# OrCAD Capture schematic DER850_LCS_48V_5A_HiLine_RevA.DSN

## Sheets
1 PAGE2: size B
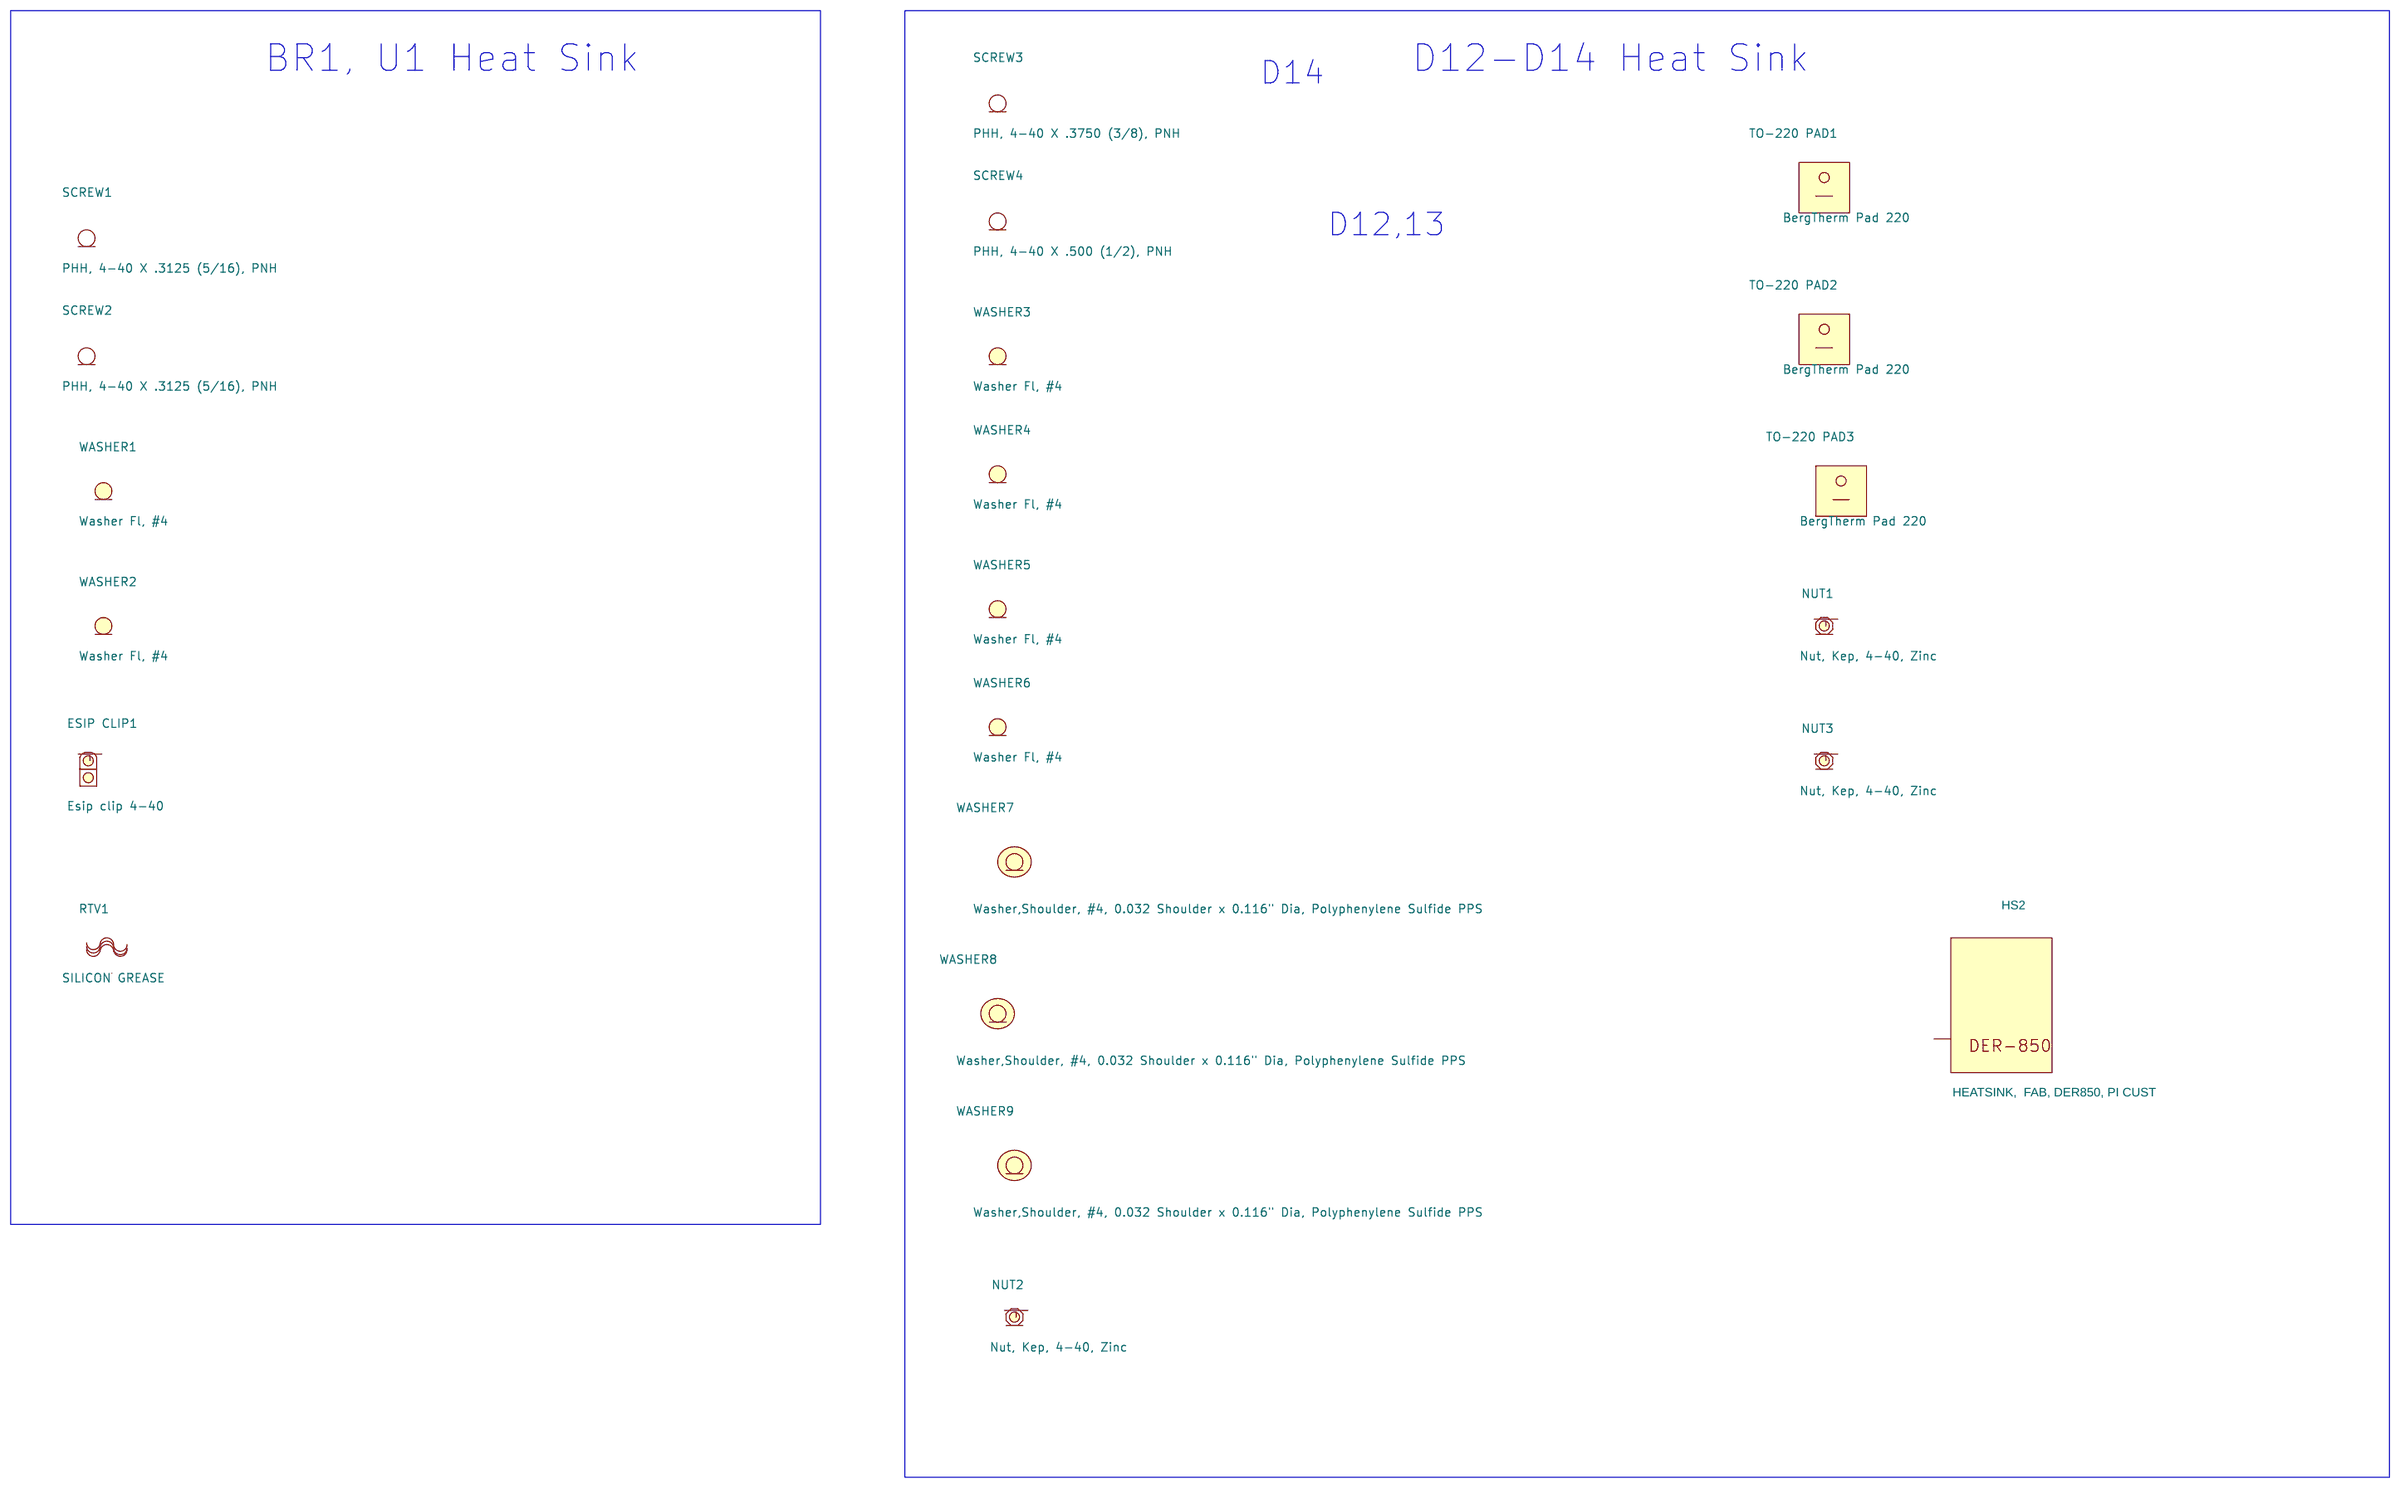
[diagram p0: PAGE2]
2 PAGE1: size C; title: DER-447; rev: D
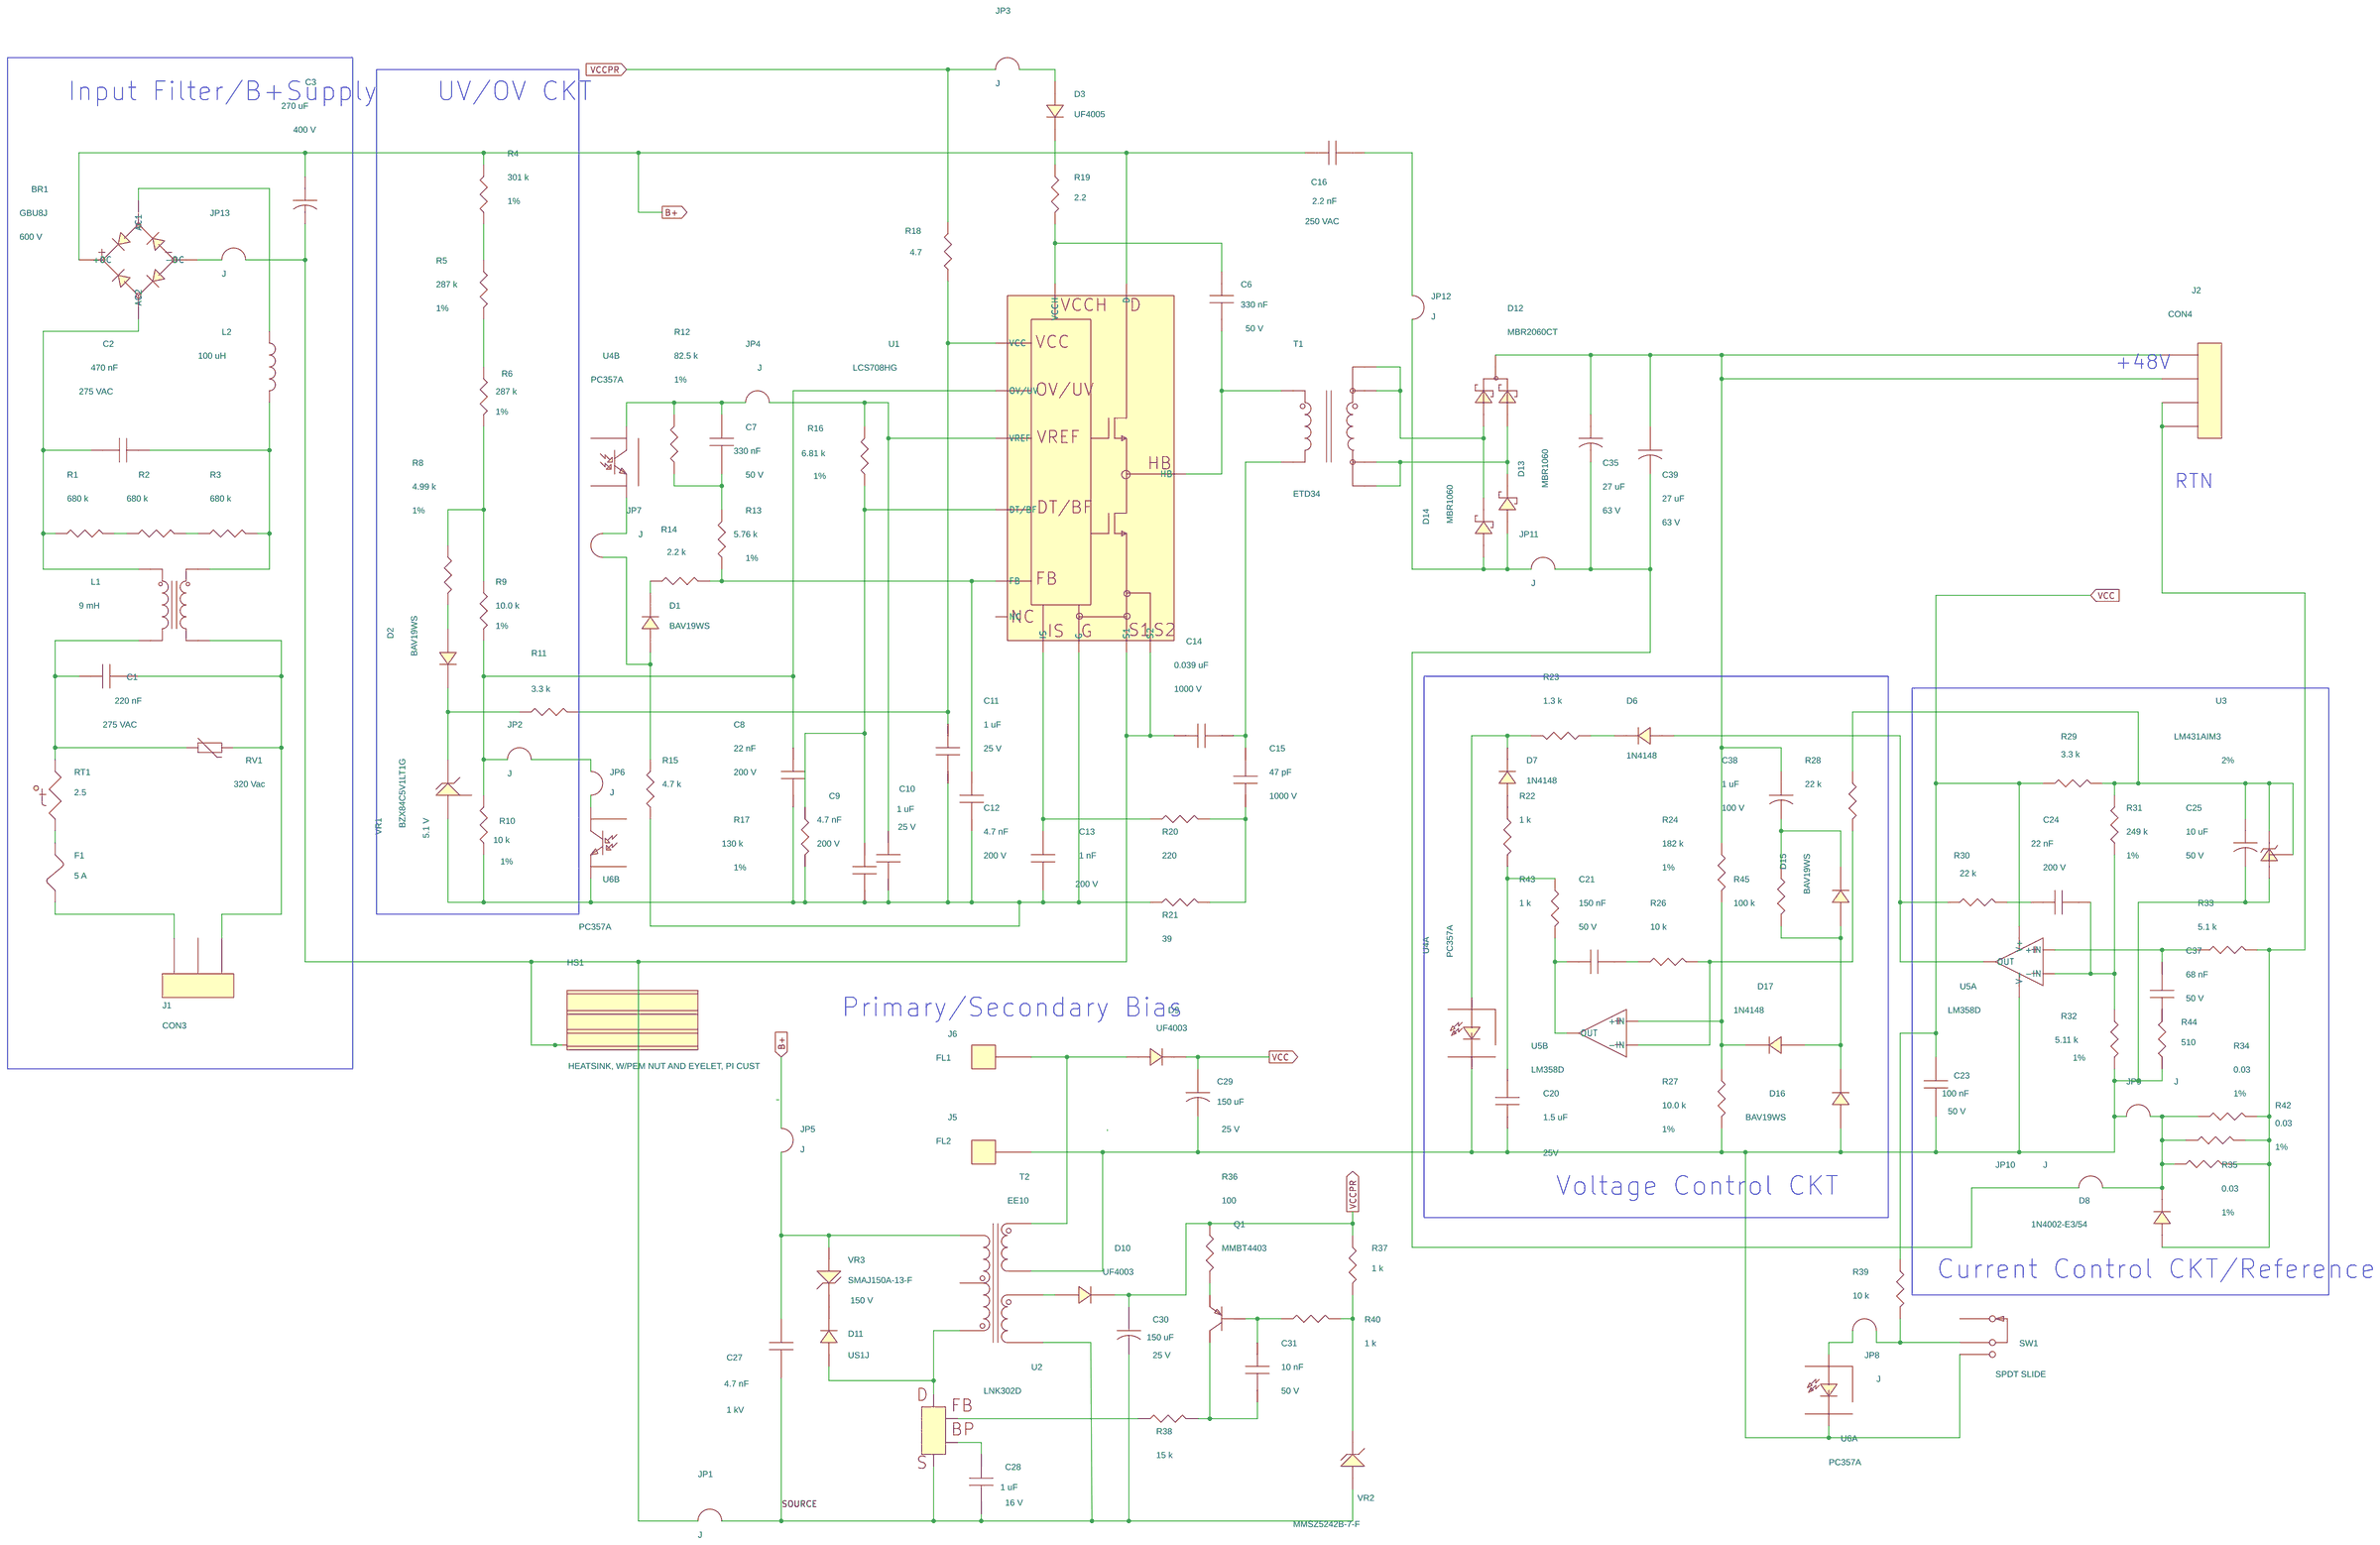
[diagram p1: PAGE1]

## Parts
sheet PAGE1
BR1  GBU8J  [pidaxbridgegbu8]
C1  220 nF  [pinpxcaprad720x340590040]
C2  470 nF  [pinpcaprad760x380590050]
C3  270 uF  [pipolcapclyd948ls394080]
C6  330 nF  [pinpcaprad200x100200030]
C7  330 nF  [pismc0805]
C8  22 nF  [pismc0805]
C9  4.7 nF  [pismc0805]
C10  1 uF  [pismc1206]
C11  1 uF  [pismc1206]
C12  4.7 nF  [pismc0805]
C13  1 nF  [pismc0805]
C14  0.039 uF  [pinpcap23x8x20mmLSd040]
C15  47 pF  [pinpcaprad370x156250040]
C16  2.2 nF  [pinpycaprad540x290ls400040]
C20  1.5 uF  [pismc1206]
C21  150 nF  [pismc0805]
C23  100 nF  [pismc0805]
C24  22 nF  [pismc0805]
C25  10 uF  [pipolcapclyd200ls80030]
C27  4.7 nF  [pinpcaprad370x156250040]
C28  1 uF  [pismc0603]
C29  150 uF  [pipolcapcyld250ls100030]
C30  150 uF  [pipolcapcyld250ls100030]
C31  10 nF  [pismc0805]
C35  27 uF  [pipolcapclyd320ls140030]
C37  68 nF  [pismc0805]
C38  1 uF  [pipolcapclyd200ls80030]
C39  27 uF  [pipolcapclyd320ls140030]
D1  BAV19WS  [pismsod323]
D2  BAV19WS  [pismsod323]
D3  UF4005  [pidax475x125040do41]
D6  1N4148  [pidax375x070030do35]
D7  1N4148  [pidax375x070030do35]
D8  1N4002-E3/54  [pidv200x110x040do41]
D9  UF4003  [pidv200x110x040do41]
D10  UF4003  [pidv200x110x040do41]
D11  US1J  [pismdsma]
D12  MBR2060CT  [pidvto2203vf1]
D13  MBR1060  [pidvt0220acreva]
D14  MBR1060  [pidvt0220acreva]
D15  BAV19WS  [pismsod323]
D16  BAV19WS  [pismsod323]
D17  1N4148  [pidax375x070030do35]
F1  5 A  [pi_tr5_submin_fuse]
HS1  HEATSINK, W/PEM NUT AND EYELET, PI CUST  [pi_hs_der447_bridge_eSIP]
J1  CON3  [pi_hdr_3pin_156_lock]
J2  CON4  [PI_HDR_4PIN]
J5  FL2  [pi_hole_30awg]
J6  FL1  [pi_hole_30awg]
JP1  J  [pi_jumper700]
JP2  J  [pi_jumper400]
JP3  J  [pi_jumper900]
JP4  J  [pi_jumper300]
JP5  J  [pi_jumper1800]
JP6  J  [pi_jumper200]
JP7  J  [pi_jumper200]
JP8  J  [pi_jumper900]
JP9  J  [pi_jumper300]
JP10  J  [pi_jumper600-18awg-sld]
JP11  J  [pi_jumper300-18awg-sld]
JP12  J  [pi_jumper800]
JP13  J  [pi_jumper900-18awg-sld]
L1  9 mH  [pi_ind_4p_500x1050ls450d46]
L2  100 uH  [pi2p455x1062ls315d60]
Q1  MMBT4403  [pismsot23132]
R1  680 k  [pismr1206]
R2  680 k  [pismr1206]
R3  680 k  [pismr1206]
R4  301 k  [pi14wresd100ls400d030]
R5  287 k  [pismr1206]
R6  287 k  [pismr1206]
R8  4.99 k  [pismr0805]
R9  10.0 k  [pismr1206]
R10  10 k  [pismr0805]
R11  3.3 k  [pismr0805]
R12  82.5 k  [pismr0805]
R13  5.76 k  [pismr0805]
R14  2.2 k  [pismr1206]
R15  4.7 k  [pismr0805]
R16  6.81 k  [pi14wresd100ls400d030]
R17  130 k  [pismr0805]
R18  4.7  [pismr1206]
R19  2.2  [pi14wresd100ls400d030]
R20  220  [pismr0603]
R21  39  [pismr0805]
R22  1 k  [pismr0805]
R23  1.3 k  [pi14wresd100ls400d030]
R24  182 k  [pi14wresd100ls500d030]
R26  10 k  [pismr0805]
R27  10.0 k  [pi14wresd100ls400d030]
R28  22 k  [pi14wresd100ls500d030]
R29  3.3 k  [pi14wvresd100ls100d030]
R30  22 k  [pismr0805]
R31  249 k  [pismr0805]
R32  5.11 k  [pismr0805]
R33  5.1 k  [pi14wresd100ls400d030]
R34  0.03  [pismr1206]
R35  0.03  [pismr1206]
R36  100  [pismr0603]
R37  1 k  [pismr0603]
R38  15 k  [pismr0805]
R39  10 k  [pismr0805]
R40  1 k  [pismr0603]
R42  0.03  [pismr1206]
R43  1 k  [pismr0805]
R44  510  [pismr0603]
R45  100 k  [pismr0805]
RT1  2.5  [pi_rad180x395ls235d031]
RV1  320 Vac  [pidisc675x225ls335x140040]
SW1  SPDT SLIDE  [pi_switch_spdt_slide_pcbm_1]
T1  ETD34  [pi_xfrmr_DER850_LLC]
T2  EE10  [pi_xfrmr_DER850_Bias]
U1  LCS708HG  [pi_ic_esip16-13_oval_slot]
U2  LNK302D  [pismso8dnshort5678]
U3  LM431AIM3  [pismsot23123]
U4  PC357A  [pi_4_smd]  (sections A,B)
U5  LM358D  [pismso8]  (sections A,B)
U6  PC357A  [pi_4_smd]  (sections A,B)
VR1  BZX84C5V1LT1G  [pismsot23123]
VR2  MMSZ5242B-7-F  [pi_sm_sod-123_12]
VR3  SMAJ150A-13-F  [pismdo214ac12]
sheet PAGE2
ESIP CLIP1  Esip clip 4-40
HS2  HEATSINK,  FAB, DER850, PI CUST  [pi_hs_1p_der850]
NUT1  Nut, Kep, 4-40, Zinc
NUT2  Nut, Kep, 4-40, Zinc
NUT3  Nut, Kep, 4-40, Zinc
RTV1  SILICON GREASE
SCREW1  PHH, 4-40 X .3125 (5/16), PNH
SCREW2  PHH, 4-40 X .3125 (5/16), PNH
SCREW3  PHH, 4-40 X .3750 (3/8), PNH
SCREW4  PHH, 4-40 X .500 (1/2), PNH
TO-220 PAD1  BergTherm Pad 220
TO-220 PAD2  BergTherm Pad 220
TO-220 PAD3  BergTherm Pad 220
WASHER1  Washer Fl, #4
WASHER2  Washer Fl, #4
WASHER3  Washer Fl, #4
WASHER4  Washer Fl, #4
WASHER5  Washer Fl, #4
WASHER6  Washer Fl, #4
WASHER7  Washer,Shoulder, #4, 0.032 Shoulder x 0.116" Dia, Polyphenylene Sulfide PPS
WASHER8  Washer,Shoulder, #4, 0.032 Shoulder x 0.116" Dia, Polyphenylene Sulfide PPS
WASHER9  Washer,Shoulder, #4, 0.032 Shoulder x 0.116" Dia, Polyphenylene Sulfide PPS

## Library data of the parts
BR1 = DISCRETE_BRIDGE_+~~-: Disp_Voltage: 600 V; Part Number: 15-00720-00
C1 = CAP_NP: Disp_Voltage: 275 VAC; Part Number: 20-00386-00; Voltage: 275 VAC
C2 = CAP_NP: COMPGROUP: 1; Disp_Voltage: 275 VAC; PCB Editor PCBFP: pinpxcaprad720x340590040; Part Number: 20-00738-00; Tol: 20; Voltage: 275 VAC
C3 = CAP_POL: Disp_Voltage: 400 V; Part Number: 20-00783-00; Voltage: 400 V
C6 = CAP_NP: Disp_Voltage: 50 V; Part Number: 20-00935-00; Voltage: 50 V
C7 = CAP_NP: Disp_Voltage: 50 V; Part Number: 20-00895-00; Voltage: 50 V
C8 C24 = CAP_NP: Disp_Voltage: 200 V; Part Number: 20-00763-00; Voltage: 200 V
C9 = CAP_NP: COMPGROUP: 2; Disp_Voltage: 200 V; Layout PCB Footprint: PI_SM/C_0805; Part Number: 20-08570-00; Tol: 10; Voltage: 200 V
C10 C11 = CAP_NP: Disp_Voltage: 25 V; Part Number: 20-00897-00; Voltage: 25 V
C12 = CAP_NP: COMPGROUP: 2; Disp_Voltage: 200 V; Part Number: 20-08570-00; Tol: 10; Voltage: 200 V
C13 = CAP_NP: COMPGROUP: 2; Disp_Voltage: 200 V; Layout PCB Footprint: PI_SM/C_0805; Part Number: 20-00737-00; Tol: 10; Voltage: 200 V
C14 = CAP_NP: Disp_Voltage: 1000 V; Part Number: 20-01356-00; Voltage: 1000 V
C15 = CAP_NP: COMPGROUP: 2; Disp_Voltage: 1000 V; PCB Editor PCBFP: pinpcaprad180x160200030; Part Number: 20-08564-00; Tol: 5; Voltage: 1000 V
C16 = CAP_NP: ALT_SYMBOLS: pinpycaprad540x290ls400040h; Disp_Voltage: 250 VAC; FPLIST: pinpycaprad540x290ls400040,pinpycaprad540x290ls400040h; Part Number: 20-00376-00; Voltage: 250 VAC
C20 = CAP_NP: Disp_Voltage: 25V; Part Number: 20-01360-00; Voltage: 25 V
C21 = CAP_NP: Disp_Voltage: 50 V; Part Number: 20-01189-00; Voltage: 50 V
C23 = CAP_NP: Disp_Voltage: 50 V; Part Number: 20-00904-00; Voltage: 50 V
C25 = CAP_POL: ALT_SYMBOLS: pipolcapclyd200ls80030h; Disp_Voltage: 50 V; FPLIST: pipolcapclyd200ls80030,pipolcapclyd200ls80030h; Part Number: 20-00443-00; Voltage: 50 V
C27 = CAP_NP: COMPGROUP: 1; Disp_Voltage: 1 kV; Part Number: 20-00571-00; Voltage: 1 kV
C28 = CAP_NP: Disp_Voltage: 16 V; Part Number: 20-00540-00; Voltage: 16 V
C29 C30 = CAP_POL: COMPGROUP: 1; Disp_Voltage: 25 V; Part Number: 20-00096-00; Tol: 20; Voltage: 25 V
C31 = CAP_NP: COMPGROUP: 1; Disp_Voltage: 50 V; Part Number: 20-00965-00; Tol: 10; Voltage: 50 V
C35 C39 = CAP_POL: Disp_Voltage: 63 V; FPLIST: pipolcapclyd320ls140030,pipolcapclyd320ls140030430h; Part Number: 20-01354-00; Voltage: 63 V
C37 = CAP_NP: Disp_Voltage: 50 V; Part Number: 20-00231-00; Voltage: 50 V
C38 = CAP_POL: ALT_SYMBOLS: pipolcapclyd200ls80030h; Disp_Voltage: 100 V; FPLIST: pipolcapclyd200ls80030,pipolcapclyd200ls80030h; Part Number: 20-00448-00; Voltage: 100 V
D1 D2 D15 D16 = DIODE: Part Number: 15-00658-00
D3 = DIODE: ALT_SYMBOLS: pidax475x125040do41,pidax390x125040do41; FPLIST: pidv200x110x040do41,pidax475x125040do41,pidax390x125040do41; Part Number: 15-00109-00
D6 D7 D17 = DIODE: ALT_SYMBOLS: pidax375x070030do35,pidv100x080x030do35; FPLIST: pidv200x080x030do35,pidax375x070030do35,pidv100x080x030do35; Part Number: 15-00083-00
D8 = DIODE: ALT_SYMBOLS: pidax475x125040do41,pidv200x110x040do41wbead,pidax390x125040do41; FPLIST: pidv200x110x040do41,pidax475x125040do41,pidv200x110x040do41wbead,pidax390x125040do41; Part Number: 15-00792-00
D9 D10 = DIODE: ALT_SYMBOLS: pidax475x125040do41,pidv200x110x040do41wbead,pidax390x125040do41; COMPGROUP: 1; FPLIST: PI_DV/.200X.110X.040/DO_41,PI_DAX/.475X.125/.040/DO_41,PI_DV/.200X.110X.040/DO_41_WBEAD,PI_DAX/.390X.125/.040/DO_41; Part Number: 15-00107-00
D11 = DIODE: Part Number: 15-00494-00
D12 = DS_DUAL_CK_A_AC: ALT_SYMBOLS: pidvto2203; FPLIST: pidvto2203vf1,pidvto2203,pi_to220_mod_1; Part Number: 15-00346-00
D13 D14 = DIODE_SCHOTTKY: FPLIST: pidvt0220acreva,pi_to220aa_mod; Part Number: 15-00148-00
F1 = FUSE: COMPGROUP: 1; Part Number: 40-00005-00; Voltage: 250 V
HS1 = HS-PI_CUSTOM1: Part Number: 61-00182-01
J1 = CON3: COMPGROUP: 1; Part Number: 35-00110-00
J2 = CON4: COMPGROUP: 2; Part Number: 35-00003-00
J5 J6 = TERM_1Pin: Part Number: 35-00026-00
JP1 = JUMPER_1: Part Number: 65-00046-00
JP2 = JUMPER_1: Part Number: 65-00003-00
JP3 JP8 = JUMPER_1: Part Number: 65-00126-00
JP4 = JUMPER_1: Part Number: 65-00120-00
JP5 = JUMPER_1: Part Number: 65-00135-00
JP6 JP7 = JUMPER_1: Part Number: 65-00001-00
JP9 = JUMPER_1: Part Number: 65-00002-00
JP10 = JUMPER_1: Part Number: 65-00084-00
JP11 = JUMPER_1: Part Number: 65-00081-00
JP12 = JUMPER_1: Part Number: 65-00007-00
JP13 = JUMPER_1: Part Number: 65-00087-00
L1 = INDUCTOR_4P_REVB_0: Part Number: 30-00235-00
L2 = INDUCTOR: Part Number: 32-00210-00
Q1 = PNP_BEC: Part Number: 55-00060-00
R1-R3 = R: Part Number: 05-01420-00
R4 = R: ALT_SYMBOLS: pi14wvresd100ls125d030,pi14wvresd100ls150d030,pi14wvresd100ls200d030,pi14wvresd100ls300d030,pi14wresd100ls400d030,pi14wresd100ls500d030; Disp_Tol: 1%; FPLIST: pi14wvresd100ls100d030,pi14wvresd100ls125d030,pi14wvresd100ls150d030,pi14wvresd100ls200d030,pi14wvresd100ls300d030,pi14wresd100ls400d030,pi14wresd100ls500d030; Part Number: 05-02214-00
R5 R6 = R: COMPGROUP: 2; Disp_Tol: 1%; Part Number: 05-00429-00; Tol: 1%
R8 = R: COMPGROUP: 2; Disp_Tol: 1%; PCB Editor PCBFP: pismr1206; Part Number: 05-03373-00; Tol: 1%
R9 = R: COMPGROUP: 2; Disp_Tol: 1%; Part Number: 05-00289-00; Tol: 1%
R10 = R: Disp_Tol: 1%; Part Number: 05-00684-00
R11 = R: Part Number: 05-01531-00
R12 = R: Disp_Tol: 1%; Part Number: 05-00772-00
R13 = R: Disp_Tol: 1%; Part Number: 05-03379-00
R14 = R: Part Number: 05-01360-00
R15 = R: COMPGROUP: 2; Part Number: 05-01535-00; Tol: 5%
R16 = R: ALT_SYMBOLS: pi14wvresd100ls200d030,pi14wresd100ls400d030,pi14wresd100ls500d030; Disp_Tol: 1%; FPLIST: pi14wvresd100ls100d030,pi14wvresd100ls200d030,pi14wresd100ls400d030,pi14wresd100ls500d030; Part Number: 05-02056-00
R17 = R: Disp_Tol: 1%; Part Number: 05-00791-00
R18 = R: Part Number: 05-01296-00
R19 = R: ALT_SYMBOLS: pi14wvresd100ls125d030,pi14wvresd100ls150d030,pi14wvresd100ls200d030,pi14wvresd100ls300d030,pi14wresd100ls400d030,pi14wresd100ls500d030; FPLIST: pi14wvresd100ls100d030,pi14wvresd100ls125d030,pi14wvresd100ls150d030,pi14wvresd100ls200d030,pi14wvresd100ls300d030,pi14wresd100ls400d030,pi14wresd100ls500d030; Part Number: 05-02443-00
R20 = R: Part Number: 05-01672-00
R21 = R: Part Number: 05-01485-00
R22 R43 = R: Part Number: 05-01519-00
R23 = R: ALT_SYMBOLS: pi14wvresd100ls125d030,pi14wvresd100ls150d030,pi14wvresd100ls200d030,pi14wvresd100ls300d030,pi14wresd100ls400d030,pi14wresd100ls500d030; FPLIST: pi14wvresd100ls100d030,pi14wvresd100ls125d030,pi14wvresd100ls150d030,pi14wvresd100ls200d030,pi14wvresd100ls300d030,pi14wresd100ls400d030,pi14wresd100ls500d030; Part Number: 05-02510-00
R24 = R: ALT_SYMBOLS: pi14wvresd100ls200d030,pi14wresd100ls400d030,pi14wresd100ls500d030; Disp_Tol: 1%; FPLIST: pi14wvresd100ls100d030,pi14wvresd100ls200d030,pi14wresd100ls400d030,pi14wresd100ls500d030; Part Number: 05-02193-00
R26 R39 = R: Part Number: 05-01543-00
R27 = R: ALT_SYMBOLS: pi14wvresd100ls200d030,pi14wresd100ls400d030,pi14wresd100ls500d030; Disp_Tol: 1%; FPLIST: pi14wvresd100ls100d030,pi14wvresd100ls200d030,pi14wresd100ls400d030,pi14wresd100ls500d030; Part Number: 05-05421-00
R28 = R: ALT_SYMBOLS: pi14wvresd100ls125d030,pi14wvresd100ls150d030,pi14wvresd100ls200d030,pi14wvresd100ls300d030,pi14wresd100ls400d030,pi14wresd100ls500d030; FPLIST: pi14wvresd100ls100d030,pi14wvresd100ls125d030,pi14wvresd100ls150d030,pi14wvresd100ls200d030,pi14wvresd100ls300d030,pi14wresd100ls400d030,pi14wresd100ls500d030; Part Number: 05-02539-00
R29 = R: ALT_SYMBOLS: pi14wvresd100ls200d030,pi14wresd100ls400d030,pi14wresd100ls500d030; FPLIST: pi14wvresd100ls100d030,pi14wvresd100ls200d030,pi14wresd100ls400d030,pi14wresd100ls500d030; Part Number: 05-02519-00
R30 = R: Part Number: 05-01551-00
R31 = R: Disp_Tol: 1%; Part Number: 05-00818-00
R32 = R: Disp_Tol: 1%; Part Number: 05-03374-00
R33 = R: ALT_SYMBOLS: pi14wvresd100ls125d030,pi14wvresd100ls150d030,pi14wvresd100ls200d030,pi14wvresd100ls300d030,pi14wresd100ls400d030,pi14wresd100ls500d030; COMPGROUP: 5; FPLIST: pi14wvresd100ls100d030,pi14wvresd100ls125d030,pi14wvresd100ls150d030,pi14wvresd100ls200d030,pi14wvresd100ls300d030,pi14wresd100ls400d030,pi14wresd100ls500d030; PCB Editor PCBFP: pismr0805; Part Number: 05-02524-00; Tol: 1%
R34 R35 R42 = R: Disp_Tol: 1%; Part Number: 05-06436-00
R36 = R: Part Number: 05-01664-00
R37 R40 = R: Part Number: 05-01688-00
R38 = R: COMPGROUP: 1; Part Number: 05-01547-00
R44 = R: COMPGROUP: 5; PCB Editor PCBFP: pismr0805; Part Number: 05-01681-00; Tol: 1%
R45 = R: Part Number: 05-01567-00
RT1 = THERMISTOR: FPLIST: pi_rad180x395ls235d031,pirad550x410ls300040_h; Part Number: 90-00038-00
RV1 = VARISTOR: COMPGROUP: 1; Part Number: 85-00009-00
SW1 = SW_SLIDE-SPDT: Part Number: 66-00111-00
T1 = BETD_34_DER850_LLC: Part Number: 25-01172-00
T2 = BEE_10_DER850_Bias: Part Number: 25-01168-00
U1 = LC_SWITCH_Rev03: ALT_SYMBOLS: pi_ic_esip16-13_socket_sl0t,pi_ic_esip16-13_oval_slot; FPLIST: pi_ic_esip16-13_slot,pi_ic_esip16-13_socket_sl0t ,pi_ic_esip16-13_oval_slot; Part Number: 10-00515-00
U2 = LNK30X_SO8_DN: Part Number: 10-00232-00
U3 = TL431_SOT-23_CAR: Disp_Tol: 2%; Part Number: 45-00268-00; Tol: 2%
U4 U6 = OPTO_A_B: Part Number: 53-00033-00
U5 = LM358: Part Number: 45-00050-00
VR1 = DIODE_ZENERC2A1: Disp_Voltage: 5.1 V; Part Number: 15-000630-00
VR2 = DIODE_ZENER: COMPGROUP: 1; Part Number: 15-01090-00
VR3 = DIODE_ZENER: Disp_Voltage: 150 V; Part Number: 15-00428-00
ESIP CLIP1 = EsipClip_4-40: Part Number: 60-00037-00
HS2 = hs_1P_DER850: Part Number: 61-00271-01
NUT1-NUT3 = NUT_HEX_4-40: Part Number: 75-00068-00
RTV1 = RTV: Part Number: 66-00084-00
SCREW1 SCREW2 = SCR_4-40: Part Number: 75-00002-00
SCREW3 = SCR_4-40: Part Number: 75-00003-00
SCREW4 = SCR_4-40: Part Number: 75-00004-00
TO-220 PAD1-TO-220 PAD3 = Berguist_TO-220_Pad: Part Number: 66-00079-00
WASHER1-WASHER6 = WASH_FLAT_4: Part Number: 75-00164-00
WASHER7-WASHER9 = WASH_SHLDR_4: Part Number: 75-00152-00

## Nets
VCC: C23.1 C29.1 D9.1 R29.1 R39.1 U5.8(V+)
VCCPR: C30.1 D10.1 JP3.1 R18.1 R36.1 R37.1
B+: BR1.1(+DC) C3.1 C16.1 JP5.1 R4.2 U1.16(D)
SOURCE: C27.2 C28.2 C30.2 JP1.2 T2.5 U2.5(S) U2.6(SOURCE) U2.7(SOURCE) U2.8(SOURCE) VR2.2
N5956875: C11.1 R11.2 R18.2 U1.1(VCC)
N5956925: C8.2 C9.2 C10.2 C11.2 C12.2 C13.2 R10.2 R15.2 R17.2 R21.1 U1.4(G) U6.3(E) VR1.1
N5956929: C10.1 JP4.2 R16.1 U1.3(VREF)
N5957241: D3.1 R19.1
N6197642: C7.2 R12.2 R13.1
N6214944: C6.1 R19.2 U1.14(VCCH)
N6216380: D3.2 JP3.2
N6234122: C9.1 R16.2 R17.1 U1.7(DT/BF)
N6240208: R6.2 R8.1 R9.1
N6267022: C12.1 R13.2 R14.2 U1.6(FB)
N6283849: C14.2 C15.2 T1.3
N6289562: C7.1 JP4.1 R12.1 U4.4(C)
N6938702: C15.1 R20.2 R21.2
N6939237: C6.2 T1.6 U1.13(HB)
N7091362: C35.1 C38.1 C39.1 D12.2(K) J2.1 J2.2 R24.1
N7093005: D8.2 J2.3 J2.4 R33.2 R34.2 R35.2 R42.2
N7953071: R5.2 R6.1
N8059193: C1.1 L1.3 RT1.2 RV1.1
N8059197: F1.1 J1.1
N8059233: C2.1 L1.4 L2.2 R3.2
N8059379: R1.2 R2.1
N8059437: C1.2 J1.3 L1.2 RV1.2
N8059489: BR1.3(AC2) C2.2 L1.1 R1.1
N8070264: D6.1 R23.1
N8070276: C25.1 R28.1 R29.2 R31.2 U3.1(C) U3.3(VREF)
N8070304: C21.1 R43.2 U5.7(OUT)
N8070334: D17.1 R24.2 R27.1 U5.5(+IN)
N8070354: C20.1 C23.2 C25.2 C29.2 D16.2 J5.1 JP9.1 R27.2 R32.2 R44.1 SW1.3 U3.2(A) U4.2(C) U5.4(V-) U6.2(C)
N8070466: R26.2 R28.2 U5.6(-IN)
N8070490: D6.2 R30.1 U5.1(OUT)
N8070648: C24.2 R31.1 R32.1 U5.2(-IN)
N8073568: C3.2 C14.1 HS1.1 JP1.1 JP13.2 U1.10(S1) U1.11(S2)
N8075340: C13.1 R20.1 U1.8(IS)
N8076366: C8.1 JP2.1 R9.2 R10.1 U1.5(OV/UV)
N8076448: C16.2 JP12.1
N8079055: D7.1 R23.2 U4.1(A)
N8088388: F1.2 RT1.1
N8091793: D2.2 R8.2
N8091974: D2.1 R11.1 VR1.2
N8094723: R37.2 R40.2 VR2.1
N8094759: C31.2 Q1.3(COLLECTOR) R38.1
N8094763: R38.2 U2.2(FB)
N8095081: Q1.2(EMITTER) R36.2
N8095089: C28.1 U2.1(BP)
N8095536: D11.2 T2.4 U2.4(D)
N8096951: C31.1 Q1.1(BASE) R40.1
N8097697: D9.2 J6.1
N8106560: D1.2 JP7.1 R15.1
N8123728: D8.1 JP9.2 JP10.2 R34.1 R35.1 R42.1
N8130547: JP8.2 R39.2 SW1.2
N8131154: JP8.1 U6.1(A)
N8135210: C24.1 R30.2
N8181225: R4.1 R5.1
N8231213: BR1.2(AC1) L2.1
N8233629: D12.1(A1) D14.1 T1.7 T1.8
N8233891: D13.2 D14.2 JP11.1 JP12.2
N8234616: D12.3(A2) D13.1 T1.11 T1.12
N8234966: C35.2 C39.2 JP10.1 JP11.2
N8241021: C37.2 R33.1 U5.3(+IN)
N8243259: C20.2 R22.2 R43.1
N8254175: C27.1 JP5.2 T2.1 VR3.2
N8276702: R2.2 R3.1
N8291038: C38.2 D15.1 R45.1
N8291055: D15.2 D16.1 D17.2 R45.2
N8302888: JP7.2 U4.3(E)
N8302918: D1.1 R14.1
N8303536: JP6.2 U6.4(C)
N8303591: JP2.2 JP6.1
N8304521: BR1.4(-DC) JP13.1
N8305228: C37.1 R44.2
N8311567: C21.2 R26.1
N8322201: D10.2 T2.6
N8337841: D7.2 R22.1
N8337842: D11.1 VR3.1

Not connected (* = marked no-connect by the designer): HS2 1; J1 2; SW1 1; T2 2; U1 9(NC); VR1 3

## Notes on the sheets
sheet 1
- BR1, U1 Heat Sink
- D12-D14 Heat Sink
- D14
- D12,13
sheet 2
- Input Filter/B+Supply
- UV/OV CKT
- +48V
- RTN
- Primary/Secondary Bias
- Voltage Control CKT
- Current Control CKT/Reference
